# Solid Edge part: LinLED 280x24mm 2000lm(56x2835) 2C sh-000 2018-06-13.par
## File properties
Subject: LinLED 280x24mm 2000lm(56x2835) 2C
Author: radoslaw.kuczynski
Template: iso metric part.par
Last saved by: radoslaw.kuczynski
Revision: 2
Application: Solid Edge
Username: radoslaw.kuczynski
Gęstość: 0,000 kg/m^3
Dokładność: 0,990
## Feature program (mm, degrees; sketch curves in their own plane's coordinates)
body "unnamed Body 1"
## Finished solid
Body 1: solid body, 1511 faces, 3882 edges, 2514 vertices, 3 separate solids.
  Faces by surface: plane 1192, cylinder 137, spline 96, cone 30, swept 22, sphere 16, torus 10, spun 8
  Edges by curve: line 3208, curve on surface 358, circle 186, ellipse 66, spline 60, intersection 4
Bounding box of the edges (mm; curved faces can reach further): 280.000 x 4.500 x 24.000, from (-140, -3.5, -12) to (140, 1, 12).
Cylindrical faces by radius (mm): R0.2 x46, R0.2169 x6, R0.25 x16, R0.3373 x6, R0.4 x8, R0.4006 x2, R0.4008 x2, R0.525 x2, R0.6 x20, R0.75 x1, R1 x8, R1.1 x4, R1.2 x10, R2.15 x6
Conical faces (half-angle, radius in mm at the cone's reference point): 0.5 deg R0.5056 x4, 0.5 deg R1.0082 x4, 1 deg R0.5511 x2, 10 deg R0.2132 x4, 10 deg R0.4132 x4, 18.8604 deg R1.0669 x4, 27.363 deg R0.6214 x2, 45 deg R0.575 x2, 45 deg R0.625 x4
Toroidal faces (ring radius, tube radius in mm): R0.8 r0.2 x4, R0.8522 r0.3 x2, R0.9002 r0.2 x2, R0.9018 r0.2 x2
Spherical faces by radius (mm): R0.2 x12, R0.6 x4
Planar faces by outward normal: +x 143, +y 13, +z 152, -x 143, -y 211, -z 156, oblique 374
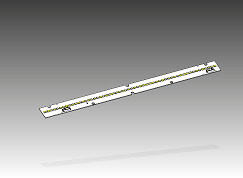
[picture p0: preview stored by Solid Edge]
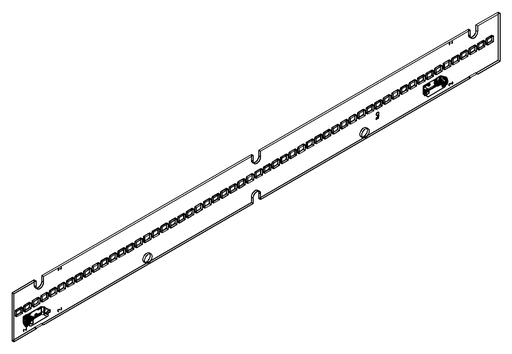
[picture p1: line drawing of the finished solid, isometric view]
